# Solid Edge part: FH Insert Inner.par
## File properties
Title: FH Insert Inner
Author: Dan
Template: FH Insert .par
Last saved by: Dan
Revision: 24
Application: Solid Edge
Density: 7833.000 kg/m^3
Accuracy: 0.990
Material: Steel
Face Style: Steel
Fill Style: ANSI32(Steel)
Virtual Style: Machined steel
Coef. of Thermal Exp: 1.3e-05
Thermal Conductivity: 32.0
Specific Heat: 481.0
Modulus of Elasticity: 199947953000.0
Poisson's Ratio: 0.29
Yield Stress: 262000766.0
Ultimate Stress: 358527364.0
Elongation: 0.0
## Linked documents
FH Insert .par
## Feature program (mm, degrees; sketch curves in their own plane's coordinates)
part copy "CopiedPart_1"
sketch for "ExtrudedProtrusion_1" plane through (0, 0, -36) normal (0, 0, -1) x-axis (-1, 0, 0)
  circle centre (0, 0) radius 22
extrude "ExtrudedProtrusion_1" add finite 5 along -normal
sketch for "Hole_1" plane through (0, 0, -36) normal (0, 0, -1) x-axis (-1, 0, 0)
  hole centre (0, 0) bore radius 9
hole "Hole_1" finite  CounterBoreDepth = 2.2 mm
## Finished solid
Body 1: solid body, 15 faces, 14 edges, 1 vertex.
  Faces by surface: plane 7, cylinder 5, cone 3
  Edges by curve: circle 14
Bounding box of the edges (mm): 44.000 x 44.000 x 42.000, from (-22, -22, -36) to (22, 22, 6).
Cylindrical faces by radius (mm): R8.5 x1, R9 x1, R12.5 x1, R18.8116 x1, R22 x1
Conical faces (half-angle, radius in mm at the cone's reference point): 1 deg R18.3793 x1, 2 deg R17.0012 x1, 59 deg R9 x1
Planar faces by outward normal: +z 5, -z 2
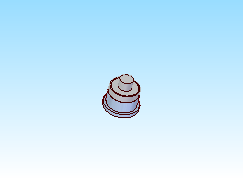
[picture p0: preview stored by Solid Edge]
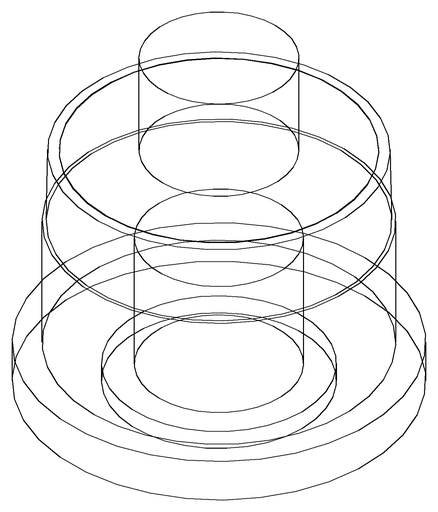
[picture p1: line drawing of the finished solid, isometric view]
